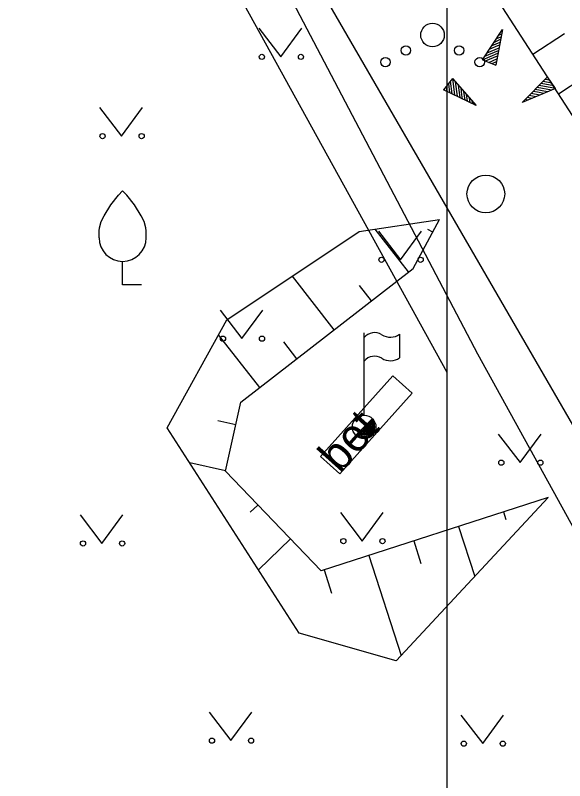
# Model space of a CAD drawing. Extents: x 554947 to 555436, y 6564938 to 6565792.
# Drawn here: x 555230.43 to 555242.09, y 6565114.23 to 6565130.48 of the extents above; entities that cross this region are included whole.
import ezdxf

# ---------------------------------------------------------------- set-up
doc = ezdxf.new("R2010")
doc.units = 0
for name, color, linetype in [('HALJASTUS', 7, 'Continuous'), ('MPKAABEL', 7, 'Continuous'), ('POST', 7, 'Continuous'), ('PR_SIDE', 7, 'Continuous'), ('PUU', 7, 'Continuous'), ('RAJATIS', 7, 'Continuous'), ('RELJEEF', 7, 'Continuous'), ('TEE', 7, 'Continuous'), ('VORMISTUS', 7, 'Continuous')]:
    doc.layers.add(name, color=color, linetype=linetype)

msp = doc.modelspace()

# ---------------------------------------------------------------- linework, layer by layer
at = {"layer": 'HALJASTUS'}
for p, q in [((555235.602, 6565130.2), (555236.066, 6565129.594)), ((555236.066, 6565129.594), (555236.511, 6565130.2)), ((555232.222, 6565128.518), (555232.685, 6565127.911)), ((555232.685, 6565127.911), (555233.131, 6565128.518)), ((555238.142, 6565125.893), (555238.605, 6565125.287)), ((555238.605, 6565125.287), (555239.051, 6565125.893)), ((555234.776, 6565124.22), (555235.24, 6565123.613)), ((555235.24, 6565123.613), (555235.685, 6565124.22)), ((555240.681, 6565121.586), (555241.145, 6565120.98)), ((555241.145, 6565120.98), (555241.59, 6565121.586)), ((555237.331, 6565119.921), (555237.794, 6565119.315)), ((555237.794, 6565119.315), (555238.24, 6565119.921)), ((555231.808, 6565119.872), (555232.271, 6565119.265)), ((555232.271, 6565119.265), (555232.717, 6565119.872)), ((555234.544, 6565115.687), (555235.007, 6565115.08)), ((555235.007, 6565115.08), (555235.453, 6565115.687)), ((555239.885, 6565115.623), (555240.349, 6565115.016)), ((555240.349, 6565115.016), (555240.794, 6565115.623))]:
    msp.add_line(p, q, dxfattribs=at)
msp.add_lwpolyline([(555235.12, 6565151.155), (555232.135, 6565148.949), (555229.151, 6565146.49), (555228.521, 6565144.196), (555233.66, 6565136.637), (555246.422, 6565114.586), (555255.514, 6565098.946)], dxfattribs=at)
for centre, radius in [((555239.285, 6565130.056), 0.25), ((555238.72, 6565129.731), 0.1), ((555239.85, 6565129.731), 0.1), ((555235.665, 6565129.594), 0.055), ((555236.493, 6565129.594), 0.055), ((555238.285, 6565129.481), 0.1), ((555240.285, 6565129.481), 0.1), ((555232.284, 6565127.911), 0.055), ((555233.113, 6565127.911), 0.055), ((555240.416, 6565126.683), 0.4), ((555238.204, 6565125.287), 0.055), ((555239.033, 6565125.287), 0.055), ((555234.839, 6565123.613), 0.055), ((555235.667, 6565123.613), 0.055), ((555240.744, 6565120.98), 0.055), ((555241.573, 6565120.98), 0.055), ((555231.87, 6565119.265), 0.055), ((555232.699, 6565119.265), 0.055), ((555237.393, 6565119.315), 0.055), ((555238.222, 6565119.315), 0.055), ((555234.606, 6565115.08), 0.055), ((555235.435, 6565115.08), 0.055), ((555239.948, 6565115.016), 0.055), ((555240.776, 6565115.016), 0.055)]:
    msp.add_circle(centre, radius, dxfattribs=at)
at = {"layer": 'MPKAABEL'}
msp.add_lwpolyline([(555252.588, 6565101.946), (555250.157, 6565105.485), (555246.43, 6565112.048), (555243.328, 6565117.686), (555240.248, 6565123.284), (555235.885, 6565131.607), (555233.393, 6565136.173), (555233.034, 6565137.981), (555233.62, 6565138.358), (555237.1, 6565137.907), (555242.704, 6565136.954), (555245.573, 6565136.455), (555256.506, 6565134.49), (555262.887, 6565133.288), (555269.268, 6565132.087), (555280.849, 6565129.896), (555289.168, 6565128.301), (555288.207, 6565123.189), (555286.959, 6565118.589), (555293.983, 6565117.646), (555297.167, 6565117.091)], dxfattribs=at)
at = {"layer": 'POST'}
msp.add_line((555237.657, 6565121.561), (555238.011, 6565121.914), dxfattribs=at)
msp.add_circle((555237.834, 6565121.737), 0.25, dxfattribs=at)
for radius, start, end in [(0.225, 224.8541, 45.0356), (0.2, 224.8427, 45.047), (0.175, 224.8281, 45.0616), (0.15, 224.8087, 45.081), (0.125, 224.7814, 45.1083), (0.1, 224.7406, 45.1491), (0.075, 224.6725, 45.2172), (0.05, 224.5363, 45.3534), (0.025, 224.1278, 45.7619)]:
    msp.add_arc((555237.834, 6565121.737), radius, start, end, dxfattribs=at)
at = {"layer": 'PR_SIDE'}
msp.add_lwpolyline([(555231.314, 6565137.915), (555239.586, 6565122.902)], dxfattribs=at)
at = {"layer": 'PUU'}
for p, q in [((555232.71, 6565124.753), (555232.71, 6565125.253)), ((555233.11, 6565124.753), (555232.71, 6565124.753))]:
    msp.add_line(p, q, dxfattribs=at)
for points in [[(555232.21, 6565125.753), (555232.21, 6565125.903), (555232.22, 6565125.968), (555232.255, 6565126.098), (555232.315, 6565126.218), (555232.46, 6565126.453), (555232.62, 6565126.658), (555232.71, 6565126.753)], [(555233.21, 6565125.753), (555233.21, 6565125.903), (555233.2, 6565125.968), (555233.165, 6565126.098), (555233.105, 6565126.218), (555232.96, 6565126.453), (555232.8, 6565126.658), (555232.71, 6565126.753)]]:
    msp.add_lwpolyline(points, dxfattribs=at)
msp.add_arc((555232.71, 6565125.753), 0.5, 180, 0, dxfattribs=at)
at = {"layer": 'RAJATIS'}
for p, q in [((555237.834, 6565121.987), (555237.834, 6565123.737)), ((555238.587, 6565123.706), (555238.587, 6565123.206)), ((555237.834, 6565121.737), (555237.834, 6565121.737))]:
    msp.add_line(p, q, dxfattribs=at)
for centre, radius, start, end in [((555238.057, 6565123.452), 0.288, 57.8941, 140.7366), ((555238.391, 6565123.985), 0.341, 237.8941, 305.0219), ((555238.057, 6565122.952), 0.288, 57.8941, 140.7366), ((555238.391, 6565123.485), 0.341, 237.8941, 305.0219)]:
    msp.add_arc(centre, radius, start, end, dxfattribs=at)
at = {"layer": 'RELJEEF'}
for p, q in [((555240.347, 6565129.532), (555240.767, 6565130.172)), ((555240.767, 6565130.172), (555240.627, 6565129.417)), ((555241.954, 6565128.812), (555244.214, 6565130.273)), ((555240.642, 6565129.982), (555240.742, 6565130.022)), ((555240.692, 6565130.057), (555240.752, 6565130.082)), ((555240.742, 6565130.132), (555240.762, 6565130.142)), ((555241.411, 6565129.652), (555242.087, 6565130.089)), ((555240.547, 6565129.832), (555240.717, 6565129.907)), ((555240.597, 6565129.907), (555240.727, 6565129.967)), ((555240.622, 6565129.812), (555240.707, 6565129.847)), ((555240.347, 6565129.532), (555240.672, 6565129.672)), ((555240.397, 6565129.607), (555240.682, 6565129.727)), ((555240.447, 6565129.682), (555240.697, 6565129.787)), ((555240.497, 6565129.757), (555240.622, 6565129.812)), ((555240.347, 6565129.532), (555240.627, 6565129.417)), ((555240.347, 6565129.532), (555240.347, 6565129.532)), ((555240.412, 6565129.507), (555240.662, 6565129.612)), ((555240.477, 6565129.477), (555240.652, 6565129.552)), ((555240.547, 6565129.452), (555240.642, 6565129.492)), ((555240.612, 6565129.427), (555240.627, 6565129.432)), ((555241.185, 6565128.626), (555241.725, 6565129.171)), ((555241.895, 6565128.921), (555241.725, 6565129.171)), ((555239.706, 6565129.131), (555239.521, 6565128.891)), ((555239.621, 6565129.021), (555239.646, 6565128.836)), ((555239.661, 6565129.076), (555239.696, 6565128.806)), ((555239.706, 6565129.131), (555240.211, 6565128.561)), ((555239.706, 6565129.131), (555239.751, 6565128.781)), ((555239.706, 6565129.131), (555239.706, 6565129.131)), ((555239.766, 6565129.066), (555239.806, 6565128.756)), ((555241.855, 6565128.976), (555241.59, 6565129.031)), ((555241.815, 6565129.036), (555241.63, 6565129.071)), ((555241.775, 6565129.096), (555241.675, 6565129.116)), ((555241.735, 6565129.156), (555241.715, 6565129.156)), ((555240.211, 6565128.561), (555239.521, 6565128.891)), ((555239.531, 6565128.906), (555239.536, 6565128.886)), ((555239.576, 6565128.961), (555239.591, 6565128.861)), ((555239.826, 6565128.996), (555239.861, 6565128.731)), ((555239.886, 6565128.931), (555239.901, 6565128.791)), ((555239.941, 6565128.861), (555239.971, 6565128.676)), ((555241.895, 6565128.921), (555241.185, 6565128.626)), ((555241.51, 6565128.841), (555241.42, 6565128.861)), ((555241.725, 6565128.851), (555241.46, 6565128.901)), ((555241.81, 6565128.886), (555241.505, 6565128.946)), ((555241.895, 6565128.921), (555241.545, 6565128.986)), ((555241.895, 6565128.921), (555241.895, 6565128.921)), ((555239.901, 6565128.791), (555239.916, 6565128.701)), ((555240.001, 6565128.796), (555240.021, 6565128.651)), ((555240.061, 6565128.726), (555240.076, 6565128.626)), ((555241.31, 6565128.676), (555241.25, 6565128.691)), ((555241.395, 6565128.711), (555241.29, 6565128.731)), ((555241.475, 6565128.746), (555241.335, 6565128.776)), ((555241.56, 6565128.781), (555241.375, 6565128.816)), ((555241.645, 6565128.816), (555241.51, 6565128.841)), ((555240.121, 6565128.661), (555240.131, 6565128.596)), ((555240.181, 6565128.591), (555240.186, 6565128.571)), ((555241.225, 6565128.641), (555241.21, 6565128.646)), ((555238.777, 6565125.027), (555238.069, 6565125.938)), ((555239.292, 6565125.874), (555239.185, 6565125.931)), ((555237.198, 6565123.8), (555236.311, 6565124.941)), ((555237.988, 6565124.414), (555237.735, 6565124.739)), ((555235.62, 6565122.572), (555234.747, 6565123.694)), ((555236.409, 6565123.186), (555236.13, 6565123.545)), ((555235.112, 6565121.78), (555234.732, 6565121.865)), ((555234.893, 6565120.804), (555234.136, 6565120.973)), ((555235.58, 6565120.081), (555235.419, 6565119.926)), ((555240.789, 6565119.935), (555240.84, 6565119.775)), ((555239.837, 6565119.627), (555240.181, 6565118.565)), ((555236.273, 6565119.361), (555235.594, 6565118.707)), ((555238.886, 6565119.319), (555239.04, 6565118.841)), ((555237.934, 6565119.011), (555238.621, 6565116.887)), ((555236.983, 6565118.704), (555237.142, 6565118.211))]:
    msp.add_line(p, q, dxfattribs=at)
for points in [[(555267.243, 6565100.718), (555264.574, 6565104.451), (555253.061, 6565121.25), (555242.65, 6565138.338), (555234.145, 6565148.829), (555233.386, 6565148.636), (555231.367, 6565148.23), (555230.85, 6565146.543), (555236.09, 6565137.882), (555248.799, 6565118.225), (555259.289, 6565103.411), (555261.934, 6565099.868)], [(555241.74, 6565120.242), (555238.516, 6565116.774), (555236.459, 6565117.362), (555233.657, 6565121.718), (555234.922, 6565124.01), (555237.725, 6565125.887), (555239.436, 6565126.14)], [(555241.74, 6565120.242), (555236.924, 6565118.685), (555234.892, 6565120.797), (555235.219, 6565122.261), (555238.876, 6565125.104), (555239.436, 6565126.14)]]:
    msp.add_lwpolyline(points, dxfattribs=at)
at = {"layer": 'TEE'}
msp.add_lwpolyline([(555238.44, 6565122.823), (555238.85, 6565122.456), (555237.32, 6565120.742), (555236.909, 6565121.109), (555238.44, 6565122.823)], dxfattribs=at)
at = {"layer": 'VORMISTUS'}
msp.add_lwpolyline([(555029.586, 6565234.913), (555239.586, 6565234.913), (555239.586, 6564937.913), (555029.586, 6564937.913)], close=True, dxfattribs=at)

# ---------------------------------------------------------------- texts
at = {"layer": 'TEE'}
msp.add_text('bet', height=0.7, rotation=48.2234, dxfattribs=at).set_placement((555237.325, 6565120.731))

doc.saveas('drawing.dxf')
